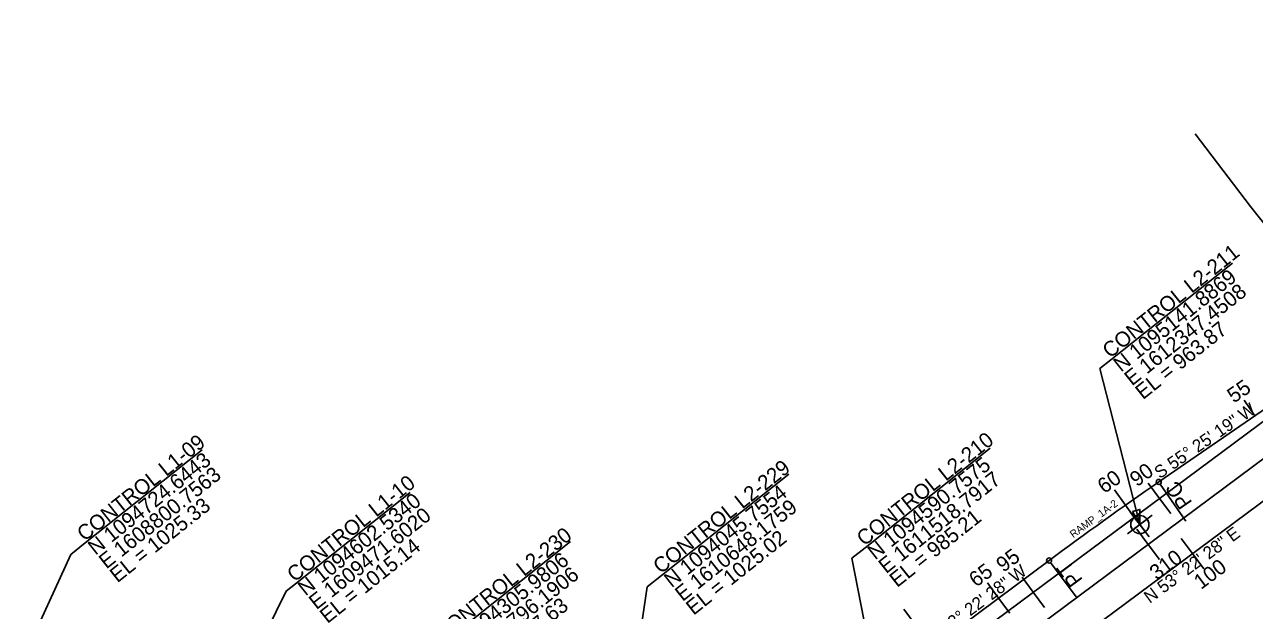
# Model space of a CAD drawing. Extents: x 1603447 to 1622636, y 1083818 to 1103958.
# Drawn here: x 1608801 to 1612712, y 1094869 to 1096732 of the extents above; entities that cross this region are included whole.
import ezdxf

# ---------------------------------------------------------------- set-up
doc = ezdxf.new("R2010")
doc.units = 0
for name, color, linetype in [('Level 1', 7, 'Continuous'), ('RD_HC_Points', 7, 'Continuous'), ('RD_HC_SUR_Bearing_TX400', 7, 'Continuous'), ('RD_HC_SUR_CL400', 7, 'Continuous'), ('RD_HC_SUR_PC_PT_400', 7, 'Continuous'), ('RD_HC_SUR_Tic400', 7, 'Continuous'), ('RD_HC_SUR_TX_Sta400', 7, 'Continuous'), ('RD_SHT_Misc1', 7, 'Continuous'), ('RD_TX_Misc1', 7, 'Continuous')]:
    doc.layers.add(name, color=color, linetype=linetype)

msp = doc.modelspace()

# ---------------------------------------------------------------- linework, layer by layer
at = {"layer": 'RD_HC_Points'}
for p, q in [((1612641.6, 1095973), (1612255.1, 1095665.6)), ((1609365.7, 1095379), (1608993.9, 1095083.3)), ((1611871.6, 1095385.1), (1611473.4, 1095068.3)), ((1611231.2, 1095302.2), (1610826.1, 1094979.9)), ((1610026.6, 1095244), (1609661.8, 1094953.8)), ((1610537.3, 1095087.9), (1610131.9, 1094765.4))]:
    msp.add_line(p, q, dxfattribs=at)
for points in [[(1612255.1, 1095665.6), (1612220, 1095637.7), (1612347.5, 1095141.9)], [(1608993.9, 1095083.3), (1608947.8, 1095046.6), (1608800.8, 1094724.6)], [(1611473.4, 1095068.3), (1611431.1, 1095034.6), (1611518.8, 1094590.8)], [(1610826.1, 1094979.9), (1610780.2, 1094943.4), (1610648.2, 1094045.8)], [(1609661.8, 1094953.8), (1609632.3, 1094930.3), (1609471.6, 1094602.5)]]:
    msp.add_lwpolyline(points, dxfattribs=at)
msp.add_lwpolyline([(1612323.9, 1095183.7), (1612347.5, 1095141.9), (1612347.9, 1095189.9)], close=True, dxfattribs=at)
at = {"layer": 'RD_HC_SUR_CL400'}
for p, q in [((1614436.6, 1096731.7), (1611265.2, 1094374.2)), ((1609261, 1092765), (1614429, 1096606.7)), ((1612699.6, 1096153.3), (1612522.9, 1096384.4)), ((1612982.5, 1095673.6), (1612407.5, 1095277.3)), ((1612190.2, 1094808.2), (1612928.5, 1095357.1)), ((1612058.8, 1095027.6), (1611687.1, 1094751.4))]:
    msp.add_line(p, q, dxfattribs=at)
for centre, radius, start, end in [((1614328.1, 1097398.4), 2050, 217.402, 257.7882), ((1619217.8, 1085397), 12000, 124.57794, 126.62559)]:
    msp.add_arc(centre, radius, start, end, dxfattribs=at)
at = {"layer": 'RD_HC_SUR_PC_PT_400'}
for p, q in [((1612412, 1095270.7), (1612493.6, 1095152.3)), ((1612063.6, 1095021.2), (1612144.6, 1094912.2)), ((1611682.4, 1094757.8), (1611596.6, 1094873.2))]:
    msp.add_line(p, q, dxfattribs=at)
for centre in [(1612407.5, 1095277.3), (1612058.8, 1095027.6)]:
    msp.add_circle(centre, 8, dxfattribs=at)
at = {"layer": 'RD_HC_SUR_Tic400'}
for p, q in [((1612713.1, 1095487.9), (1612679, 1095537.3)), ((1612630.7, 1095431.2), (1612630.7, 1095431.2)), ((1612650.6, 1095404), (1612650.6, 1095404)), ((1612548.4, 1095374.4), (1612548.4, 1095374.4)), ((1612466.1, 1095317.7), (1612466.1, 1095317.7)), ((1612570.4, 1095344.4), (1612570.4, 1095344.4)), ((1612694.9, 1095317.6), (1612694.9, 1095317.6)), ((1612409.9, 1095225.1), (1612374.1, 1095273.2)), ((1612490.1, 1095284.7), (1612490.1, 1095284.7)), ((1612301.8, 1095203.6), (1612267.2, 1095252.6)), ((1612383.7, 1095260.9), (1612383.7, 1095260.9)), ((1612614.6, 1095257.9), (1612614.6, 1095257.9)), ((1612301.8, 1095203.6), (1612336.4, 1095154.6)), ((1612409.9, 1095225.1), (1612445.7, 1095176.9)), ((1612534.3, 1095198.3), (1612534.3, 1095198.3)), ((1612329.6, 1095165.4), (1612329.6, 1095165.4)), ((1612675.4, 1095168.9), (1612675.4, 1095168.9)), ((1612220.3, 1095145.6), (1612220.3, 1095145.6)), ((1612373.8, 1095079), (1612338, 1095127.1)), ((1612454.1, 1095138.6), (1612454.1, 1095138.6)), ((1612139.3, 1095087), (1612139.3, 1095087)), ((1612249.4, 1095105.8), (1612249.4, 1095105.8)), ((1612373.8, 1095079), (1612409.6, 1095030.8)), ((1612514.9, 1095049.6), (1612479.1, 1095097.8)), ((1612595.2, 1095109.3), (1612595.2, 1095109.3)), ((1612169.1, 1095046.1), (1612169.1, 1095046.1)), ((1612514.9, 1095049.6), (1612550.7, 1095001.4)), ((1612058.8, 1095027.6), (1612058.8, 1095027.6)), ((1612293.6, 1095019.3), (1612293.6, 1095019.3)), ((1612008.6, 1094926.8), (1611972.8, 1094974.9)), ((1611978.5, 1094968), (1611978.5, 1094968)), ((1612088.9, 1094986.4), (1612088.9, 1094986.4)), ((1612213.3, 1094959.7), (1612213.3, 1094959.7)), ((1612434.7, 1094989.9), (1612434.7, 1094989.9)), ((1611898.3, 1094908.3), (1611862.5, 1094956.5)), ((1612008.6, 1094926.8), (1612044.4, 1094878.6)), ((1612354.4, 1094930.3), (1612354.4, 1094930.3)), ((1611898.3, 1094908.3), (1611934.1, 1094860.2)), ((1612133.1, 1094900), (1612133.1, 1094900)), ((1612274.2, 1094870.6), (1612274.2, 1094870.6))]:
    msp.add_line(p, q, dxfattribs=at)
at = {"layer": 'RD_SHT_Misc1'}
for p, q in [((1612308.6, 1095112.4), (1612386.3, 1095171.4)), ((1612317.9, 1095180.7), (1612377, 1095103.1)), ((1612347.5, 1095141.9), (1612330, 1095164.8)), ((1612370.3, 1095159.3), (1612347.5, 1095141.9)), ((1612324.6, 1095124.5), (1612347.5, 1095141.9)), ((1612347.5, 1095141.9), (1612364.9, 1095119))]:
    msp.add_line(p, q, dxfattribs=at)
msp.add_circle((1612347.5, 1095141.9), 28.8, dxfattribs=at)
for start, end in [(127.2464, 217.2464), (307.2464, 37.2464)]:
    msp.add_arc((1612347.5, 1095141.9), 28.8, start, end, dxfattribs=at)

# ---------------------------------------------------------------- texts
at = {"layer": 'Level 1'}
for s, rotation, p in [('55', 34.5779, (1612646.4, 1095526.4)), ('95', 36.6256, (1611913.3, 1094988.1)), ('65', 36.6256, (1611826.8, 1094941.1))]:
    msp.add_text(s, height=48, rotation=rotation, dxfattribs=at).set_placement(p)
at = {"layer": 'RD_HC_Points'}
for s, p in [('CONTROL L2-211', (1612252.6, 1095668.7)), ('N 1095141.8869', (1612287.5, 1095624.9)), ('E 1612347.4508', (1612322.3, 1095581)), ('EL = 963.87', (1612357.2, 1095537.2)), ('CONTROL L2-210', (1611470.9, 1095071.4)), ('CONTROL L1-09', (1608991.4, 1095086.4)), ('N 1094724.6443', (1609026.3, 1095042.6)), ('N 1094590.7575', (1611505.7, 1095027.6)), ('E 1608800.7563', (1609061.1, 1094998.8)), ('CONTROL L2-229', (1610823.6, 1094983.1)), ('E 1611518.7917', (1611540.6, 1094983.8)), ('CONTROL L1-10', (1609659.3, 1094956.9)), ('N 1094602.5340', (1609694.2, 1094913.1)), ('N 1094045.7554', (1610858.5, 1094939.2)), ('EL = 1025.33', (1609096, 1094954.9)), ('E 1609471.6020', (1609729, 1094869.3)), ('E 1610648.1759', (1610893.3, 1094895.4)), ('EL = 985.21', (1611575.5, 1094940)), ('CONTROL L2-230', (1610129.4, 1094768.5)), ('EL = 1025.02', (1610928.2, 1094851.6)), ('EL = 1015.14', (1609763.9, 1094825.4)), ('N 1094305.9806', (1610164.3, 1094724.7)), ('E 1609796.1906', (1610199.1, 1094680.9)), ('EL = 1007.63', (1610234, 1094637))]:
    msp.add_text(s, height=48, rotation=38.4995, dxfattribs=at).set_placement(p)
at = {"layer": 'RD_HC_SUR_Bearing_TX400'}
for s, rotation, p in [('S 55%%d 25\' 19" W', 34.5779, (1612411, 1095285.9)), ('N 53%%d 22\' 28" E', 36.6256, (1612379.1, 1094889.6)), ('S 53%%d 22\' 28" W', 36.6256, (1611690.7, 1094762.1))]:
    msp.add_text(s, height=40, rotation=rotation, dxfattribs=at).set_placement(p)
at = {"layer": 'RD_HC_SUR_PC_PT_400'}
for s, rotation, p in [('PC', 124.5779, (1612515.7, 1095211.9)), ('PT', 126.6256, (1612167.5, 1094966))]:
    msp.add_text(s, height=48, rotation=rotation, dxfattribs=at).set_placement(p)
at = {"layer": 'RD_HC_SUR_TX_Sta400'}
for s, rotation, p in [('60', 35.1932, (1612234.3, 1095238.4)), ('90', 36.6256, (1612338.1, 1095260.1)), ('310', 36.6256, (1612401.1, 1094963.2)), ('100', 36.6256, (1612541.9, 1094933.6))]:
    msp.add_text(s, height=48, rotation=rotation, dxfattribs=at).set_placement(p)
at = {"layer": 'RD_TX_Misc1'}
msp.add_text('RAMP_1A-2', height=24, rotation=36.3016, dxfattribs=at).set_placement((1612135.8, 1095098))

doc.saveas('drawing.dxf')
